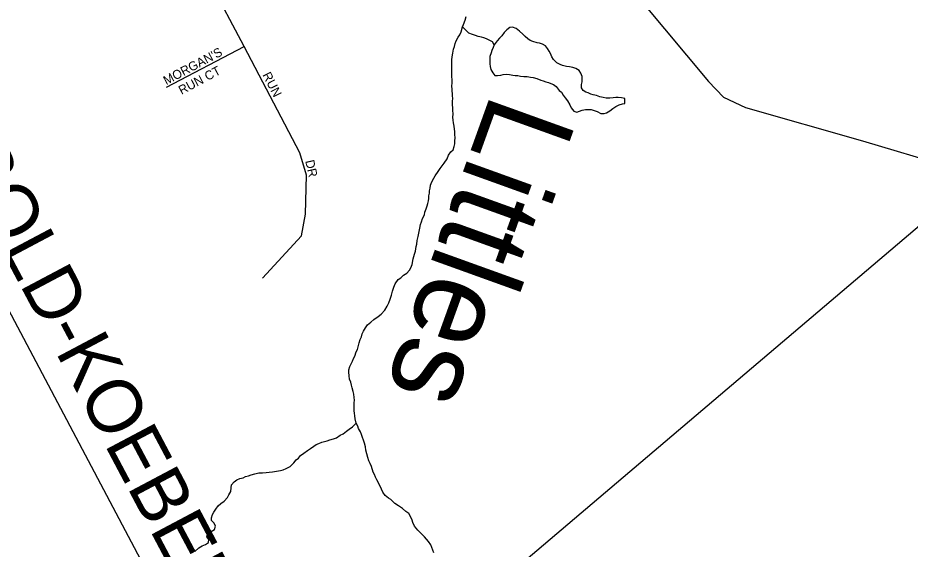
# Model space of a CAD drawing. Extents: x 1310247 to 1664935, y 284496 to 704931.
# Drawn here: x 1507726 to 1512676, y 477604 to 480550 of the extents above; entities that cross this region are included whole.
import ezdxf

# ---------------------------------------------------------------- set-up
doc = ezdxf.new("R2010")
doc.units = 0
for name, color, linetype in [('GM_P_State_Location', 7, 'Continuous'), ('GM_X_County_Road_Text', 7, 'Continuous'), ('GM_X_County_Subdivision_Text', 7, 'Continuous'), ('GM_X_Minor_Lake_Text', 7, 'Continuous'), ('GM_X_Minor_River', 7, 'Continuous'), ('GM_X_Minor_River_Text', 7, 'Continuous'), ('GM_X_State_Location', 7, 'Continuous'), ('GM_X_Township_Subdivision', 7, 'Continuous')]:
    doc.layers.add(name, color=color, linetype=linetype)

msp = doc.modelspace()

# ---------------------------------------------------------------- linework, layer by layer
at = {"layer": 'GM_X_County_Road_Text'}
for points in [[(1507656.8, 481545.3), (1507686.7, 481533.1), (1507879.9, 481454.2), (1508443, 481329.6), (1508833.5, 481255.6), (1509699.6, 481023.7), (1509984.2, 480993.4), (1510151.1, 481010.4), (1510359.7, 481059.4), (1510468, 481118.6), (1510672.9, 481181.2), (1510756.3, 481198.3), (1511068.5, 480783.7), (1511557.6, 480196.4), (1511640.6, 480110.9), (1511762.2, 480052.9), (1512412.2, 479868.3), (1512884, 479728.6)], [(1502889.8, 471015.5), (1503751.1, 471629.3), (1503878, 471716.3), (1504204.3, 471981.9), (1505333.7, 472949.9), (1508647.1, 475751.9), (1509141.1, 476182.7), (1509251.1, 476281.3), (1509536.8, 476696), (1509623.1, 476823), (1509670.2, 476876.4), (1509810.6, 476992.5), (1510141.7, 477234.1), (1510336.7, 477375.5), (1510507.6, 477513.2), (1513011.2, 479638.4)]]:
    msp.add_lwpolyline(points, dxfattribs=at)
at = {"layer": 'GM_X_County_Subdivision_Text'}
msp.add_lwpolyline([(1506817.7, 480546.1), (1508644.4, 477096), (1509141.1, 476182.7)], dxfattribs=at)
at = {"layer": 'GM_X_Minor_River'}
for points in [[(1510954.4, 480112.3), (1510936.5, 480118.7), (1510918.5, 480123.2), (1510904.6, 480127.5), (1510890.7, 480133.9), (1510876.7, 480138.2), (1510862.9, 480146.6), (1510853.2, 480162.9), (1510853.7, 480180.9), (1510856, 480194.9), (1510856.4, 480209), (1510856.8, 480225), (1510849.2, 480243.2), (1510839.5, 480257.5), (1510821.7, 480270), (1510805.8, 480274.4), (1510785.8, 480278.9), (1510769.8, 480281.3), (1510747.8, 480285.8), (1510733.9, 480292.2), (1510716, 480300.6), (1510698.4, 480319.1), (1510688.7, 480333.4), (1510681.1, 480351.6), (1510673.4, 480365.8), (1510663.7, 480380.1), (1510654.1, 480394.4), (1510636.2, 480404.9), (1510620.3, 480409.3), (1510606.3, 480411.6), (1510582.3, 480418.2), (1510568.4, 480424.6), (1510554.6, 480432.9), (1510540.9, 480447.3), (1510527.1, 480459.7), (1510509.4, 480476.2), (1510489.7, 480490.7), (1510469.8, 480499.2), (1510455.7, 480497.5), (1510439.3, 480483.9), (1510424.9, 480468.2), (1510410.4, 480450.5), (1510398, 480436.7), (1510385.6, 480423), (1510369, 480399.8)], [(1510369, 480399.8), (1510362.5, 480385.4), (1510356.1, 480369.5), (1510351.8, 480355.6), (1510345.2, 480335.6), (1510344.8, 480315.6), (1510344.2, 480295.5), (1510345.9, 480279.5), (1510349.5, 480263.3), (1510361.1, 480245), (1510372.8, 480230.6), (1510386.8, 480230.3), (1510405, 480231.9), (1510419.1, 480235.5), (1510437.2, 480237.1), (1510453.3, 480236.7), (1510471.3, 480232.3), (1510485.3, 480229.9), (1510499.3, 480229.6), (1510515.3, 480227.2), (1510533.3, 480224.8), (1510551.4, 480224.3), (1510569.4, 480221.9), (1510585.4, 480219.5), (1510605.4, 480213), (1510627.3, 480204.4), (1510641.2, 480200.1), (1510655.2, 480195.7), (1510669.1, 480191.4), (1510683.1, 480187), (1510697, 480180.7), (1510712.8, 480170.3), (1510728.3, 480147.8), (1510742.1, 480137.5), (1510751.8, 480121.2), (1510761.5, 480106.9), (1510775.1, 480090.5), (1510788.6, 480068.1), (1510796.2, 480051.9), (1510809.9, 480033.5), (1510827.8, 480027), (1510842, 480032.7), (1510856.2, 480038.4), (1510874.3, 480042), (1510888.4, 480041.6), (1510906.5, 480041.2), (1510922.4, 480036.8), (1510940.4, 480030.3), (1510960.2, 480019.8), (1510978.2, 480019.4), (1510992.4, 480023.1), (1511010.8, 480034.7), (1511027.2, 480048.3), (1511043.5, 480058), (1511061.8, 480067.5), (1511080, 480073.1), (1511094.1, 480074.8)], [(1511094.1, 480074.8), (1511092.8, 480102.9), (1511074.8, 480107.4), (1511056.8, 480107.8), (1511042.7, 480108.1), (1511028.6, 480106.5), (1511010.5, 480104.9), (1510990.4, 480105.4), (1510972.4, 480107.8), (1510954.4, 480112.3)]]:
    msp.add_lwpolyline(points, dxfattribs=at)
at = {"layer": 'GM_X_Minor_River_Text'}
for points in [[(1510058.3, 479698.5), (1510068.7, 479714.3), (1510079.2, 479730.1), (1510091.5, 479743.8), (1510108.2, 479767.5), (1510114.8, 479789.4), (1510127.3, 479807.1), (1510141.6, 479818.8), (1510146.1, 479836.8), (1510150.4, 479850.8), (1510150.9, 479868.8), (1510151.3, 479884.8), (1510149.7, 479902.9), (1510150.1, 479919), (1510146.9, 479949.1), (1510143.3, 479967.3), (1510141.7, 479983.4), (1510140.1, 479999.5), (1510140.5, 480015.5), (1510139, 480037.6), (1510139.3, 480051.7), (1510137.7, 480067.8), (1510138.2, 480087.8), (1510138.6, 480103.8), (1510137, 480117.9), (1510135.9, 480156.1), (1510134.2, 480170.2), (1510134.8, 480192.2), (1510135.2, 480208.3), (1510133.5, 480222.4), (1510133.9, 480238.4), (1510134.5, 480260.5), (1510133, 480282.6), (1510133.5, 480302.6), (1510133.8, 480316.7), (1510136.3, 480334.7), (1510138.8, 480354.7), (1510143.4, 480376.6), (1510147.7, 480390.6), (1510152.2, 480408.5), (1510158.5, 480422.4), (1510169.1, 480442.2), (1510177.5, 480456.1), (1510185.9, 480471.9), (1510192.6, 480499.8), (1510199, 480513.7), (1510207.6, 480537.6), (1510214.1, 480557.5)], [(1510369, 480399.8), (1510359.3, 480417.6), (1510341.5, 480426), (1510325.6, 480434.4), (1510311.6, 480438.8), (1510297.7, 480443.1), (1510279.7, 480447.6), (1510265.8, 480451.9), (1510247.8, 480458.4), (1510227.9, 480464.9), (1510192.6, 480499.8)], [(1509743.4, 477936.3), (1509731.9, 477960.6), (1509718.6, 477989), (1509710.9, 478003.3), (1509705.2, 478017.5), (1509697.5, 478031.7), (1509688.2, 478062), (1509680.6, 478078.2), (1509673, 478094.5), (1509667.4, 478112.7), (1509661.9, 478132.9), (1509656.4, 478153.1), (1509654.8, 478171.2), (1509649.3, 478191.4), (1509643.6, 478207.6), (1509638, 478223.8), (1509632.4, 478239.9), (1509626.7, 478254.1), (1509615.1, 478272.5), (1509611.5, 478286.6), (1509603.8, 478302.8), (1509598.4, 478327), (1509594.8, 478343.2), (1509593.1, 478357.3), (1509591.5, 478371.3), (1509591.9, 478387.4), (1509592.2, 478401.4), (1509592.6, 478415.5), (1509592.9, 478429.5), (1509591.3, 478445.6), (1509589.7, 478463.7), (1509586.1, 478477.8), (1509580.6, 478498), (1509576.9, 478514.2), (1509573.3, 478530.3), (1509565.7, 478546.5), (1509564.1, 478564.6), (1509562.6, 478584.7), (1509563, 478598.8), (1509567.4, 478616.7), (1509575.9, 478632.6), (1509582.2, 478646.5), (1509588.6, 478660.4), (1509595, 478674.2), (1509603.6, 478698.1), (1509610, 478712), (1509614.3, 478726), (1509618.9, 478747.9), (1509625.4, 478765.8), (1509631.8, 478781.7), (1509636.2, 478797.7), (1509644.6, 478813.5), (1509655.1, 478831.3), (1509665.5, 478847.1), (1509684, 478862.7), (1509700.5, 478878.4), (1509725, 478893.8), (1509741.4, 478907.5), (1509762, 478929.1), (1509774.6, 478950.8), (1509785.1, 478970.6), (1509791.6, 478990.6), (1509798.2, 479012.5), (1509804.8, 479034.4), (1509811.4, 479056.3), (1509819.9, 479076.1), (1509836.5, 479099.8), (1509850.8, 479109.5), (1509865.2, 479123.2), (1509883.6, 479134.8), (1509898.1, 479150.5), (1509906.4, 479164.4), (1509912.9, 479182.3), (1509919.7, 479214.2), (1509926.4, 479240.1), (1509932.8, 479256), (1509935.5, 479282), (1509939.8, 479296), (1509942.3, 479316), (1509946.9, 479338), (1509951.4, 479355.9), (1509956.1, 479383.9), (1509960.6, 479403.8), (1509965, 479419.8), (1509971.5, 479437.7), (1509982, 479457.5), (1509984.4, 479473.5), (1509990.9, 479491.4), (1509997.3, 479507.3), (1509999.7, 479521.3), (1510004, 479535.2), (1510006.4, 479549.2), (1510006.7, 479563.3), (1510009.1, 479577.2), (1510009.4, 479591.3), (1510013.8, 479605.2), (1510016.2, 479623.2), (1510022.7, 479641.1), (1510033.2, 479660.9), (1510041.6, 479674.8), (1510058.3, 479698.5)], [(1508708.3, 477592), (1508730.9, 477611.6), (1508749.2, 477623.2), (1508767.5, 477630.8), (1508783.8, 477640.4), (1508786.3, 477658.4), (1508774.6, 477672.7), (1508778.9, 477686.6), (1508799.4, 477702.2), (1508817.8, 477713.8), (1508822.3, 477731.8), (1508814.6, 477748), (1508800.9, 477762.4), (1508801.3, 477778.4), (1508805.8, 477796.4), (1508814.2, 477810.2), (1508824.6, 477826), (1508837.1, 477843.8), (1508851.5, 477857.5), (1508869.9, 477871.1), (1508888.5, 477890.7), (1508896.9, 477904.5), (1508907.4, 477924.3), (1508909.9, 477944.3), (1508912.3, 477960.3), (1508926.8, 477978), (1508941.1, 477987.7), (1508957.4, 477995.4), (1508975.5, 477999), (1508989.8, 478006.6), (1509006, 478010.2), (1509020.2, 478015.9), (1509040.4, 478021.5), (1509062.6, 478026.9), (1509082.7, 478026.5), (1509102.9, 478030), (1509121, 478031.6), (1509139.1, 478033.1), (1509161.3, 478036.6), (1509183.5, 478040.1), (1509197.6, 478043.8), (1509213.9, 478051.4), (1509236.3, 478062.9), (1509256.8, 478082.5), (1509269.3, 478100.2), (1509283.6, 478107.9), (1509294, 478123.7), (1509312.4, 478137.3), (1509332.9, 478150.8), (1509349.2, 478162.5), (1509367.6, 478176.1), (1509381.9, 478183.8), (1509396.1, 478189.5), (1509412.4, 478197.1), (1509426.5, 478200.8), (1509442.7, 478204.4), (1509456.9, 478210.1), (1509477.1, 478215.6), (1509493.3, 478221.2), (1509513.8, 478236.8), (1509530.1, 478244.4), (1509548.5, 478258), (1509564.8, 478269.7), (1509583.3, 478283.3), (1509603.8, 478302.8)], [(1510033.9, 477584.1), (1510022.6, 477612.5), (1510017, 477628.7), (1510003.4, 477647.1), (1509981.9, 477671.7), (1509964.3, 477690.2), (1509944.6, 477708.7), (1509927.1, 477731.2), (1509917.6, 477751.5), (1509913.9, 477765.6), (1509906.3, 477781.9), (1509894.7, 477802.2), (1509878.9, 477812.6), (1509859.2, 477829.1), (1509837.5, 477843.7), (1509817.8, 477858.2), (1509796.2, 477878.8), (1509782.3, 477887.2), (1509764.6, 477901.7), (1509751, 477920), (1509743.4, 477936.3)]]:
    msp.add_lwpolyline(points, dxfattribs=at)
at = {"layer": 'GM_X_State_Location'}
for points in [[(1509084.3, 479106.9), (1509299.3, 479341.4), (1509322.7, 479462.5), (1509326.6, 479677.5), (1509291.4, 479802.5), (1508981.4, 480390.9), (1508791.2, 480752.2), (1508783.4, 480803), (1508783.4, 480865.5), (1508799, 480935.8), (1508830.3, 481076.5), (1508833.5, 481255.6)], [(1508550.9, 480166), (1508981.4, 480390.9)]]:
    msp.add_lwpolyline(points, dxfattribs=at)

# ---------------------------------------------------------------- texts
at = {"layer": 'GM_P_State_Location'}
for s, rotation, p in [("MORGAN'S", 27.9801, (1508549.7, 480176.5)), ('RUN CT', 28.0717, (1508634.2, 480122.6)), ('RUN', 297.2182, (1509081.7, 480234.1)), ('DR', 282.5237, (1509320.1, 479756.6))]:
    msp.add_text(s, height=50, rotation=rotation, dxfattribs=at).set_placement(p)
at = {"layer": 'GM_X_Minor_Lake_Text'}
msp.add_text('Littles', height=500.01, rotation=250.1919, dxfattribs=at).set_placement((1510356.7, 480145.7))
at = {"layer": 'GM_X_Township_Subdivision'}
msp.add_text('DEBOLD-KOEBEL', height=300, rotation=297.9316, dxfattribs=at).set_placement((1507096.5, 480276.3))

doc.saveas('drawing.dxf')
